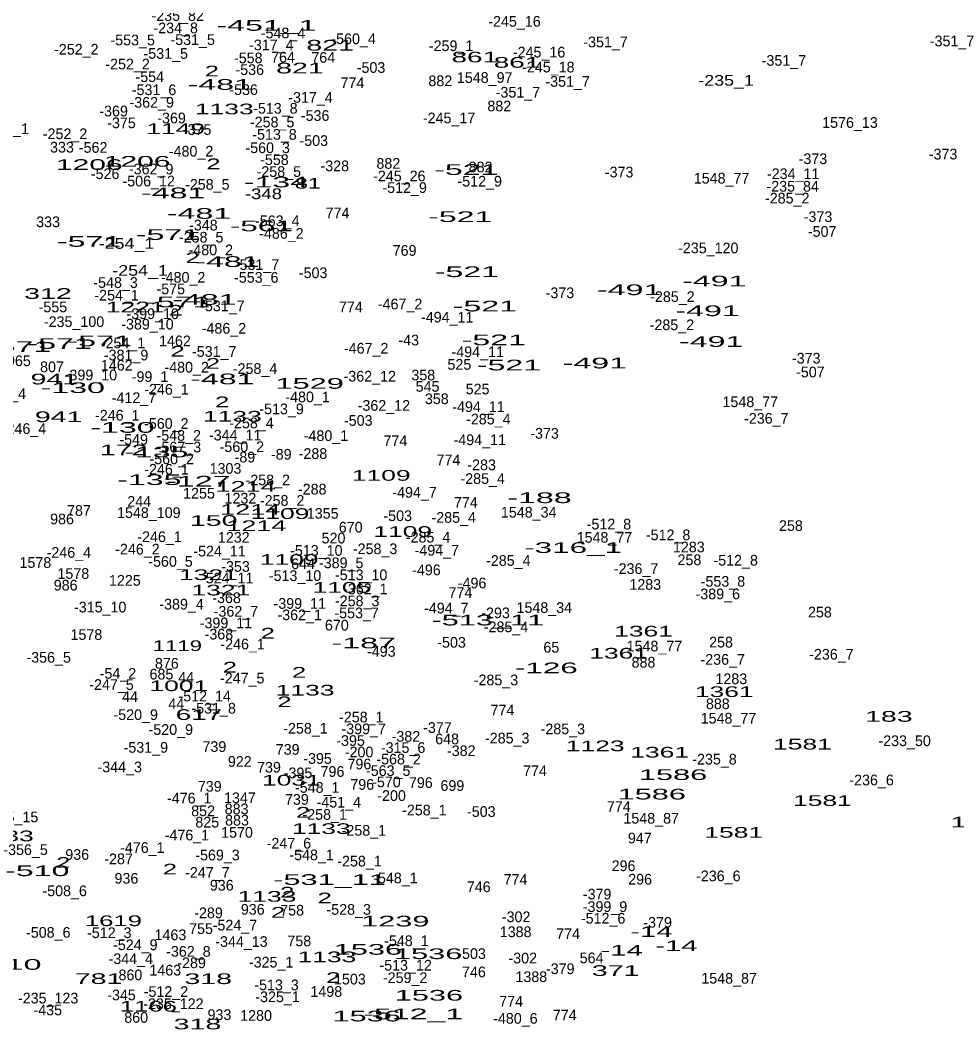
# Model space of a CAD drawing. Extents: x -660434 to -656144, y -997850 to -994016.
# Drawn here: x -658704 to -658353, y -995568.7 to -995192.7 of the extents above; entities that cross this region are included whole.
import ezdxf
from ezdxf.enums import TextEntityAlignment as Align

# ---------------------------------------------------------------- set-up
doc = ezdxf.new("R2010")
doc.units = 0
doc.header["$LTSCALE"] = 1.6
doc.layers.add('24', color=7, linetype='Continuous')

msp = doc.modelspace()

# ---------------------------------------------------------------- texts
at = {"layer": '24'}
for s, p in [('-235_82', (-658644.921, -995193)), ('-245_16', (-658518.775, -995195.16)), ('-234_8', (-658645.677, -995197.61)), ('-548_4', (-658605.471, -995199.52)), ('-553_5', (-658661.802, -995202.14)), ('-531_5', (-658639.326, -995202)), ('-317_4', (-658609.846, -995204)), ('-560_4', (-658579.036, -995201.68)), ('-259_1', (-658542.522, -995204.3)), ('-351_7', (-658484.672, -995202.87)), ('-351_7', (-658354.872, -995202.49)), ('-252_2', (-658682.912, -995205.62)), ('-531_5', (-658649.406, -995207.19)), ('-245_16', (-658509.565, -995206.68)), ('-252_2', (-658663.712, -995211.15)), ('-558', (-658618.495, -995208.85)), ('764', (-658605.473, -995208.57)), ('764', (-658590.403, -995208.67)), ('-245_18', (-658506.089, -995212.28)), ('-351_7', (-658417.852, -995209.79)), ('-554', (-658655.389, -995215.88)), ('-536', (-658617.94, -995213.24)), ('-503', (-658572.499, -995212.45)), ('774', (-658579.483, -995218.18)), ('882', (-658546.557, -995217.43)), ('1548_97', (-658529.933, -995216.2)), ('-351_7', (-658498.872, -995217.66)), ('-531_6', (-658653.792, -995220.78)), ('-536', (-658620.24, -995220.73)), ('-351_7', (-658517.482, -995221.7)), ('-362_9', (-658654.663, -995225.49)), ('-317_4', (-658595.166, -995223.63)), ('882', (-658524.467, -995226.85)), ('-369', (-658668.935, -995228.75)), ('-513_8', (-658608.336, -995227.73)), ('-536', (-658593.45, -995230.43)), ('-375', (-658665.971, -995233.17)), ('-369', (-658647.235, -995231.35)), ('-258_5', (-658609.552, -995232.88)), ('-245_17', (-658543.275, -995231.34)), ('1576_13', (-658393.103, -995233.04)), ('-563_1', (-658708.982, -995235.37)), ('-252_2', (-658687.132, -995237.27)), ('-375', (-658637.651, -995235.67)), ('-513_8', (-658608.666, -995237.49)), ('333', (-658688.287, -995242.29)), ('-562', (-658676.6, -995242.38)), ('-503', (-658593.949, -995239.81)), ('-480_2', (-658639.921, -995243.8)), ('-560_3', (-658611.232, -995242.49)), ('-373', (-658358.231, -995244.88)), ('-558', (-658608.695, -995246.96)), ('-328', (-658586.085, -995249.28)), ('882', (-658566.027, -995248.37)), ('882', (-658531.477, -995249.71)), ('-373', (-658406.991, -995246.61)), ('-526', (-658672.11, -995252.23)), ('-362_9', (-658654.863, -995250.46)), ('-258_5', (-658607.052, -995251.42)), ('-245_26', (-658561.911, -995253.07)), ('-373', (-658479.571, -995251.6)), ('-234_11', (-658414.403, -995252.23)), ('-506_12', (-658655.805, -995254.97)), ('-258_5', (-658633.832, -995256.22)), ('-512_9', (-658559.922, -995257.43)), ('-512_9', (-658531.792, -995255.03)), ('1548_77', (-658441.193, -995253.9)), ('-235_84', (-658414.566, -995256.92)), ('-285_2', (-658416.612, -995261.37)), ('774', (-658585.053, -995266.91)), ('-373', (-658405.081, -995268.31)), ('333', (-658693.467, -995270.24)), ('-348', (-658635.309, -995271.47)), ('-563_4', (-658607.632, -995269.85)), ('-258_5', (-658636.142, -995276)), ('-486_2', (-658606.092, -995274.58)), ('-507', (-658403.524, -995273.86)), ('-480_2', (-658632.531, -995280.75)), ('769', (-658559.933, -995280.95)), ('-235_120', (-658446.189, -995280.03)), ('-531_7', (-658615.222, -995286.28)), ('-480_2', (-658642.891, -995291.02)), ('-553_6', (-658615.498, -995291.06)), ('-503', (-658594.189, -995289.32)), ('-548_3', (-658668.197, -995292.98)), ('-254_1', (-658667.82, -995297.74)), ('-575', (-658647.511, -995295.36)), ('-373', (-658501.751, -995296.83)), ('-285_2', (-658459.622, -995298.25)), ('-555', (-658691.685, -995302.12)), ('-531_7', (-658628.182, -995301.73)), ('774', (-658580.063, -995302.1)), ('-467_2', (-658561.628, -995301.02)), ('-399_10', (-658654.3, -995304.67)), ('-494_11', (-658543.973, -995305.96)), ('-235_100', (-658683.753, -995307.63)), ('-389_10', (-658656.265, -995308.57)), ('-285_2', (-658459.812, -995308.82)), ('-486_2', (-658627.602, -995310.12)), ('-254_1', (-658665.42, -995315.61)), ('1462', (-658645.96, -995314.84)), ('-467_2', (-658574.338, -995317.59)), ('-43', (-658558.379, -995314.52)), ('-381_9', (-658664.262, -995320.14)), ('-531_7', (-658631.252, -995318.81)), ('-494_11', (-658532.543, -995318.93)), ('-373', (-658409.491, -995321.32)), ('965', (-658704.408, -995322.28)), ('807', (-658692.017, -995324.55)), ('1462', (-658667.75, -995323.96)), ('-480_2', (-658641.561, -995324.69)), ('525', (-658539.417, -995323.65)), ('-399_10', (-658677.43, -995327.61)), ('-99_1', (-658655.297, -995328.21)), ('-258_4', (-658615.947, -995325.2)), ('-362_12', (-658572.981, -995328.07)), ('358', (-658552.947, -995327.62)), ('-507', (-658407.944, -995326.49)), ('545', (-658551.341, -995331.89)), ('-246_4', (-658710.076, -995334.64)), ('-412_7', (-658661.306, -995336.11)), ('-246_1', (-658649.136, -995332.97)), ('-480_1', (-658596.294, -995335.82)), ('525', (-658532.597, -995332.87)), ('-362_12', (-658567.701, -995339.01)), ('358', (-658547.867, -995336.52)), ('-494_11', (-658532.263, -995339.48)), ('1548_77', (-658430.443, -995337.64)), ('-246_1', (-658667.566, -995342.68)), ('-513_9', (-658606.032, -995340.3)), ('-236_7', (-658424.454, -995343.85)), ('-560_2', (-658649.192, -995345.78)), ('-258_4', (-658617.287, -995345.56)), ('-503', (-658577.299, -995344.64)), ('-285_4', (-658528.567, -995344.12)), ('-246_4', (-658702.496, -995347.69)), ('-548_2', (-658644.537, -995350.24)), ('-344_11', (-658623.397, -995350.12)), ('-480_1', (-658589.384, -995350.32)), ('-373', (-658507.511, -995349.46)), ('-549', (-658661.415, -995351.77)), ('-567_3', (-658644.464, -995354.61)), ('-560_2', (-658620.892, -995354.46)), ('774', (-658563.383, -995352.22)), ('-494_11', (-658531.783, -995351.87)), ('-89', (-658619.76, -995358.37)), ('-89', (-658606.12, -995357.31)), ('-288', (-658594.265, -995357.03)), ('-560_2', (-658647.172, -995359.03)), ('1303', (-658627.024, -995362.6)), ('774', (-658543.513, -995359.42)), ('-283', (-658531.075, -995361.26)), ('-246_1', (-658649.136, -995362.92)), ('-285_4', (-658530.687, -995366.4)), ('-258_2', (-658611.192, -995366.92)), ('1255', (-658636.95, -995371.9)), ('1232', (-658621.42, -995373.76)), ('-288', (-658594.545, -995370.38)), ('-494_7', (-658556.212, -995371.55)), ('244', (-658659.356, -995374.95)), ('-258_2', (-658605.812, -995374.6)), ('774', (-658536.983, -995375.36)), ('787', (-658681.919, -995378.36)), ('1548_109', (-658655.755, -995379.17)), ('1355', (-658590.62, -995379.43)), ('-503', (-658562.509, -995380.32)), ('-285_4', (-658541.537, -995380.96)), ('1548_34', (-658513.447, -995379.01)), ('986', (-658688.248, -995381.54)), ('670', (-658580.132, -995384.61)), ('-512_8', (-658483.406, -995383.47)), ('258', (-658415.237, -995384.03)), ('-246_1', (-658651.726, -995388.18)), ('1232', (-658623.92, -995388.41)), ('520', (-658586.561, -995388.7)), ('-285_4', (-658551.137, -995388.36)), ('1548_77', (-658485.073, -995388.42)), ('-512_8', (-658461.226, -995387.49)), ('-258_3', (-658570.982, -995392.71)), ('1283', (-658453.48, -995392.03)), ('-246_4', (-658685.696, -995394.06)), ('-246_2', (-658660.012, -995392.84)), ('-524_11', (-658629.263, -995393.58)), ('-513_10', (-658593.003, -995393.33)), ('-494_7', (-658547.862, -995393.25)), ('1578', (-658698.236, -995397.84)), ('-560_5', (-658647.622, -995397.43)), ('-353', (-658623.265, -995399.33)), ('644', (-658597.971, -995398.32)), ('-389_5', (-658583.688, -995397.97)), ('-285_4', (-658521.087, -995397.09)), ('-236_7', (-658473.224, -995400.13)), ('258', (-658453.237, -995396.83)), ('-512_8', (-658435.916, -995396.99)), ('1578', (-658684.026, -995401.97)), ('-524_11', (-658626.383, -995403.66)), ('-513_10', (-658600.973, -995402.75)), ('-513_10', (-658576.203, -995402.46)), ('-496', (-658551.749, -995400.62)), ('986', (-658686.898, -995406.32)), ('1225', (-658664.72, -995404.54)), ('-362_1', (-658574.652, -995407.75)), ('-496', (-658534.659, -995405.52)), ('1283', (-658469.8, -995406.06)), ('-553_8', (-658440.702, -995404.9)), ('-368', (-658626.63, -995411.04)), ('774', (-658539.003, -995409.1)), ('-389_6', (-658442.623, -995409.61)), ('-315_10', (-658673.953, -995414.54)), ('-389_4', (-658643.482, -995413.45)), ('-399_11', (-658599.22, -995413.18)), ('-258_3', (-658577.702, -995412.21)), ('-494_7', (-658544.312, -995414.92)), ('1548_34', (-658507.607, -995414.72)), ('-362_7', (-658623.124, -995416.13)), ('-362_1', (-658599.232, -995417.45)), ('-553_7', (-658577.908, -995416.72)), ('-293', (-658525.85, -995416.71)), ('258', (-658404.377, -995416.42)), ('-399_11', (-658626.86, -995420.47)), ('670', (-658585.312, -995421.3)), ('-285_4', (-658521.947, -995421.94)), ('1578', (-658679.136, -995424.82)), ('-368', (-658629.5, -995424.67)), ('-246_1', (-658620.616, -995428.39)), ('-503', (-658542.349, -995427.74)), ('65', (-658504.973, -995429.59)), ('1548_77', (-658466.353, -995429.14)), ('258', (-658441.407, -995427.67)), ('-356_5', (-658693.268, -995433.36)), ('-493', (-658568.645, -995431.14)), ('-236_7', (-658440.774, -995434.13)), ('-236_7', (-658400.064, -995432.21)), ('876', (-658648.998, -995435.6)), ('888', (-658470.447, -995435.19)), ('-54_2', (-658667.317, -995439.37)), ('685', (-658651.013, -995439.65)), ('44', (-658641.726, -995440.86)), ('-247_5', (-658620.752, -995441.15)), ('1283', (-658437.55, -995441.4)), ('-247_5', (-658669.712, -995443.55)), ('-285_3', (-658525.712, -995441.82)), ('44', (-658662.756, -995448.07)), ('-512_14', (-658634.823, -995447.87)), ('44', (-658645.476, -995450.75)), ('-531_8', (-658631.456, -995452.41)), ('888', (-658442.607, -995450.75)), ('-520_9', (-658660.662, -995454.83)), ('-258_1', (-658576.166, -995455.72)), ('774', (-658523.283, -995453.13)), ('1548_77', (-658438.623, -995456.17)), ('-520_9', (-658647.512, -995460.4)), ('-258_1', (-658597.076, -995459.94)), ('-399_7', (-658575.258, -995460.15)), ('-377', (-658547.635, -995459.66)), ('-285_3', (-658500.662, -995460.16)), ('-382', (-658559.445, -995462.95)), ('648', (-658544.017, -995463.91)), ('-285_3', (-658521.492, -995463.62)), ('-531_9', (-658656.872, -995467.09)), ('739', (-658631.188, -995466.79)), ('739', (-658603.738, -995467.84)), ('-395', (-658580.17, -995464.53)), ('-315_6', (-658560.492, -995467.16)), ('-233_50', (-658372.635, -995464.61)), ('-395', (-658592.55, -995471.25)), ('-200', (-658576.973, -995468.81)), ('-568_2', (-658562.188, -995471.47)), ('-382', (-658538.715, -995468.34)), ('-235_8', (-658443.842, -995471.5)), ('-344_3', (-658666.641, -995474.42)), ('922', (-658621.673, -995472.36)), ('739', (-658610.738, -995474.52)), ('796', (-658576.863, -995473.32)), ('-395', (-658599.85, -995476.63)), ('796', (-658586.953, -995476.11)), ('-563_5', (-658566.078, -995475.79)), ('774', (-658511.093, -995475.83)), ('739', (-658632.918, -995481.67)), ('-548_1', (-658592.66, -995482.09)), ('796', (-658575.813, -995480.96)), ('-570', (-658566.744, -995480.04)), ('796', (-658553.853, -995480.28)), ('699', (-658542.043, -995481.39)), ('-236_6', (-658385.013, -995479.3)), ('-476_1', (-658640.602, -995486.08)), ('1347', (-658621.63, -995485.97)), ('739', (-658600.278, -995486.57)), ('-200', (-658564.823, -995485.14)), ('883', (-658622.857, -995490.12)), ('-451_4', (-658584.585, -995487.61)), ('774', (-658479.693, -995489.25)), ('-245_15', (-658706.949, -995493.14)), ('852', (-658635.417, -995490.85)), ('-258_1', (-658589.876, -995492.21)), ('-258_1', (-658552.536, -995490.57)), ('-503', (-658531.209, -995491.13)), ('1548_87', (-658467.567, -995493.64)), ('825', (-658633.857, -995495.1)), ('883', (-658622.717, -995494.35)), ('-476_1', (-658641.462, -995499.91)), ('1570', (-658622.72, -995498.91)), ('-258_1', (-658575.186, -995498.16)), ('947', (-658471.823, -995501.05)), ('-356_5', (-658701.908, -995505.39)), ('-476_1', (-658658.172, -995504.62)), ('-247_6', (-658603.278, -995502.99)), ('936', (-658682.568, -995507.2)), ('-287', (-658667.071, -995508.84)), ('-569_3', (-658630.023, -995507.41)), ('-548_1', (-658594.78, -995507.35)), ('-258_1', (-658576.826, -995509.69)), ('296', (-658477.918, -995511.43)), ('936', (-658664.138, -995516.13)), ('-247_7', (-658633.818, -995513.94)), ('-548_1', (-658563.38, -995515.99)), ('774', (-658518.383, -995516.54)), ('296', (-658471.718, -995516.47)), ('-236_6', (-658442.423, -995515.22)), ('936', (-658628.428, -995518.72)), ('746', (-658532.163, -995519.3)), ('-508_6', (-658687.272, -995520.81)), ('-379', (-658487.815, -995522.05)), ('936', (-658616.808, -995527.75)), ('758', (-658602.063, -995528.06)), ('-528_3', (-658580.872, -995527.78)), ('-399_9', (-658484.868, -995526.73)), ('-289', (-658633.39, -995529.06)), ('-302', (-658518.169, -995530.54)), ('-512_6', (-658485.572, -995531.09)), ('755', (-658636.193, -995534.98)), ('-524_7', (-658623.482, -995533.67)), ('-379', (-658465.155, -995532.62)), ('-508_6', (-658693.412, -995536.37)), ('-512_3', (-658670.556, -995536.51)), ('1463', (-658647.66, -995537.28)), ('1388', (-658518.34, -995536.16)), ('774', (-658498.703, -995536.88)), ('-524_9', (-658660.802, -995541.03)), ('-344_13', (-658621.044, -995539.81)), ('758', (-658599.383, -995539.58)), ('-548_1', (-658559.26, -995539.51)), ('-344_4', (-658662.496, -995546.23)), ('-362_8', (-658640.918, -995543.49)), ('-503', (-658534.859, -995544.33)), ('-302', (-658515.679, -995546)), ('564', (-658489.887, -995545.93)), ('1463', (-658649.58, -995550.53)), ('-289', (-658639.73, -995547.77)), ('-325_1', (-658609.926, -995547.54)), ('-513_12', (-658559.539, -995548.67)), ('-379', (-658501.635, -995550)), ('860', (-658662.637, -995552.3)), ('1503', (-658580.434, -995553.88)), ('-259_2', (-658559.728, -995553.34)), ('746', (-658533.983, -995551.19)), ('1388', (-658512.48, -995552.97)), ('1548_87', (-658438.377, -995553.57)), ('-513_3', (-658607.916, -995556.04)), ('-235_123', (-658693.465, -995561)), ('-345', (-658665.979, -995559.81)), ('-512_2', (-658649.326, -995558.53)), ('-325_1', (-658607.526, -995560.51)), ('1498', (-658589.27, -995558.52)), ('-435', (-658693.589, -995565.42)), ('-235_122', (-658646.535, -995563.11)), ('774', (-658520.013, -995562.18)), ('860', (-658660.477, -995568.24)), ('933', (-658629.293, -995567.19)), ('1280', (-658615.574, -995567.49)), ('-480_6', (-658518.436, -995568.59)), ('774', (-658499.953, -995567.33))]:
    msp.add_text(s, height=4, dxfattribs=at).set_placement(p, align=Align.CENTER)
for s, width, p in [('-451_1', 2.25, (-658611.663, -995196.68)), ('821', 2, (-658587.817, -995204.1)), ('861', 1.95, (-658533.653, -995208.51)), ('861', 1.95, (-658517.833, -995210.52)), ('2', 1.8, (-658632.111, -995213.77)), ('821', 2, (-658599.137, -995212.65)), ('-481', 2.25, (-658629.166, -995218.8)), ('-235_1', 1.25, (-658439.51, -995217.25)), ('1133', 1.85, (-658627.484, -995227.97)), ('1149', 1.85, (-658645.665, -995235.37)), ('1206', 2.1, (-658678.039, -995248.79)), ('1206', 2.1, (-658660.129, -995247.59)), ('2', 1.8, (-658631.531, -995248.54)), ('-521', 2.25, (-658536.791, -995250.67)), ('-134', 2.25, (-658608.136, -995255.34)), ('81', 1.65, (-658596.177, -995255.81)), ('-481', 2.25, (-658646.636, -995259.42)), ('-348', 1.3, (-658612.81, -995259.75)), ('-481', 2.25, (-658636.946, -995267.11)), ('-521', 2.25, (-658539.091, -995268.31)), ('-561', 2.2, (-658613.615, -995271.78)), ('-571', 2.25, (-658648.575, -995275.01)), ('-571', 2.25, (-658678.115, -995277.6)), ('-254_1', 1.25, (-658664.1, -995278.34)), ('2', 1.8, (-658639.311, -995283.68)), ('-481', 2.25, (-658626.286, -995285.13)), ('-254_1', 1.25, (-658659.01, -995288.44)), ('-521', 2.25, (-658536.601, -995288.93)), ('-491', 2.25, (-658443.941, -995292.41)), ('312', 2, (-658693.517, -995297.09)), ('-491', 2.25, (-658475.811, -995295.68)), ('1221', 1.85, (-658660.854, -995302.14)), ('-571', 2.25, (-658644.735, -995300.27)), ('-481', 2.25, (-658634.926, -995299.33)), ('-521', 2.25, (-658529.881, -995301.8)), ('2', 1.8, (-658645.651, -995303.38)), ('-491', 2.25, (-658446.441, -995303.55)), ('-571', 2.25, (-658704.325, -995316.97)), ('-571', 2.25, (-658689.155, -995315.82)), ('-571', 2.25, (-658674.175, -995314.85)), ('-521', 2.25, (-658526.521, -995314.48)), ('-491', 2.25, (-658445.091, -995315.07)), ('2', 1.8, (-658644.971, -995318.69)), ('2', 1.8, (-658631.731, -995323.28)), ('-521', 2.25, (-658520.851, -995323.88)), ('-491', 2.25, (-658488.681, -995323.14)), ('941', 2, (-658691.138, -995329.14)), ('-130', 2.25, (-658684.237, -995332.36)), ('-481', 2.25, (-658628.206, -995329.08)), ('1529', 2.15, (-658595.503, -995330.77)), ('2', 1.8, (-658628.271, -995337.69)), ('941', 2, (-658689.508, -995343.26)), ('1133', 1.85, (-658624.454, -995343.08)), ('-130', 2.25, (-658665.617, -995347.25)), ('172', 2, (-658665.163, -995355.69)), ('-135', 2.25, (-658652.971, -995356.45)), ('1109', 1.85, (-658568.695, -995365.21)), ('-135', 2.25, (-658655.551, -995366.82)), ('-127', 2.25, (-658637.205, -995367.38)), ('1214', 1.9, (-658619.489, -995369.33)), ('-188', 2.25, (-658509.391, -995373.58)), ('1214', 1.9, (-658617.759, -995377.98)), ('1109', 1.85, (-658606.605, -995379.52)), ('150', 2, (-658631.444, -995382.12)), ('1214', 1.9, (-658615.449, -995384.07)), ('1109', 1.85, (-658560.635, -995386.25)), ('-316_1', 2.2, (-658496.813, -995392.26)), ('1109', 1.85, (-658603.165, -995396.71)), ('1321', 1.85, (-658633.424, -995402.41)), ('1105', 1.85, (-658583.41, -995407.17)), ('1321', 1.85, (-658628.764, -995408.17)), ('-513_11', 2.15, (-658528.754, -995419.41)), ('2', 1.8, (-658611.181, -995424.32)), ('1361', 1.85, (-658470.449, -995423.56)), ('1119', 1.55, (-658645.055, -995429)), ('-187', 2.25, (-658575.255, -995427.98)), ('1361', 1.85, (-658479.759, -995431.82)), ('2', 1.8, (-658625.381, -995437.06)), ('-126', 2.2, (-658506.835, -995437.31)), ('2', 1.8, (-658599.471, -995438.98)), ('1001', 1.85, (-658644.506, -995444.01)), ('1133', 1.85, (-658597.204, -995445.66)), ('1361', 1.85, (-658440.199, -995446.22)), ('2', 1.8, (-658604.941, -995450.02)), ('617', 1.95, (-658636.987, -995454.8)), ('183', 2, (-658378.537, -995455.48)), ('1123', 1.85, (-658488.544, -995466.51)), ('1581', 1.85, (-658410.924, -995465.88)), ('1361', 1.85, (-658464.399, -995468.89)), ('1586', 2.15, (-658459.373, -995477.3)), ('1031', 1.85, (-658602.36, -995479.38)), ('1586', 2.15, (-658467.343, -995484.6)), ('1581', 1.85, (-658403.434, -995487.01)), ('2', 1.8, (-658597.931, -995491.41)), ('1133', 1.85, (-658591.144, -995497.52)), ('183', 2, (-658346.477, -995495.05)), ('1133', 1.85, (-658709.854, -995500.24)), ('1581', 1.85, (-658436.654, -995498.92)), ('2', 1.8, (-658687.791, -995510.2)), ('2', 1.8, (-658647.851, -995512.69)), ('-510', 2.25, (-658697.527, -995513.29)), ('-531_11', 2.15, (-658588.044, -995516.6)), ('1133', 1.85, (-658611.494, -995522.88)), ('2', 1.8, (-658603.881, -995521.34)), ('2', 1.8, (-658589.871, -995523.49)), ('2', 1.8, (-658607.341, -995528.87)), ('1619', 1.8, (-658669.013, -995532.02)), ('1239', 2.15, (-658563.423, -995532.17)), ('-14', 2.05, (-658467.496, -995536.07)), ('1536', 2.15, (-658573.683, -995542.75)), ('-14', 2.05, (-658478.636, -995543.09)), ('-14', 2.05, (-658458.096, -995541.36)), ('1133', 1.85, (-658589.034, -995545.54)), ('1536', 2.15, (-658551.113, -995544.38)), ('-510', 2.25, (-658707.987, -995548.39)), ('371', 2, (-658480.873, -995550.68)), ('781', 2, (-658674.563, -995553.7)), ('318', 2, (-658633.487, -995553.73)), ('2', 1.8, (-658586.651, -995553.31)), ('1536', 2.15, (-658550.833, -995559.94)), ('1166', 1.8, (-658655.913, -995564.05)), ('1536', 2.15, (-658574.163, -995567.72)), ('-512_1', 2.25, (-658556.697, -995566.92)), ('318', 2, (-658637.537, -995570.7))]:
    msp.add_text(s, height=4, dxfattribs=dict(at, width=width)).set_placement(p, align=Align.CENTER)

doc.saveas('drawing.dxf')
